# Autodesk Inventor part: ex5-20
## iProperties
Shininess: 64.0
Length Units: 11272
Angle Units: 11279
Time Units: 11290
Mass Units: 11286
Length Display Precision: 3
Angle Display Precision: 2
Compacted: True
Part Number: ex5-20
Document SubType Name: Modeling
Created: 2003-11
Designer: Elise Moss
Cost Center: 0 lbmass
Authority: 0.89 in^3
Manufacturer: Standard
Standards Organization: Custom
Density: 0.0
Volumn: 0.0
Area: 0.0
PropertySet Name: Model Information
Control State: 0
Master: False
Checked Out: False
SaveDate: 2003-11-15
SaveTime: 20:51
TotalMass: 0 lbmass
TotalVolume: 0.89 in^3
Author: Elise Moss
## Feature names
1. Revolution1
2. Shell1
3. Extrusion2
4. Circular Pattern1
5. Rectangular Pattern1
6. Circular Pattern2
